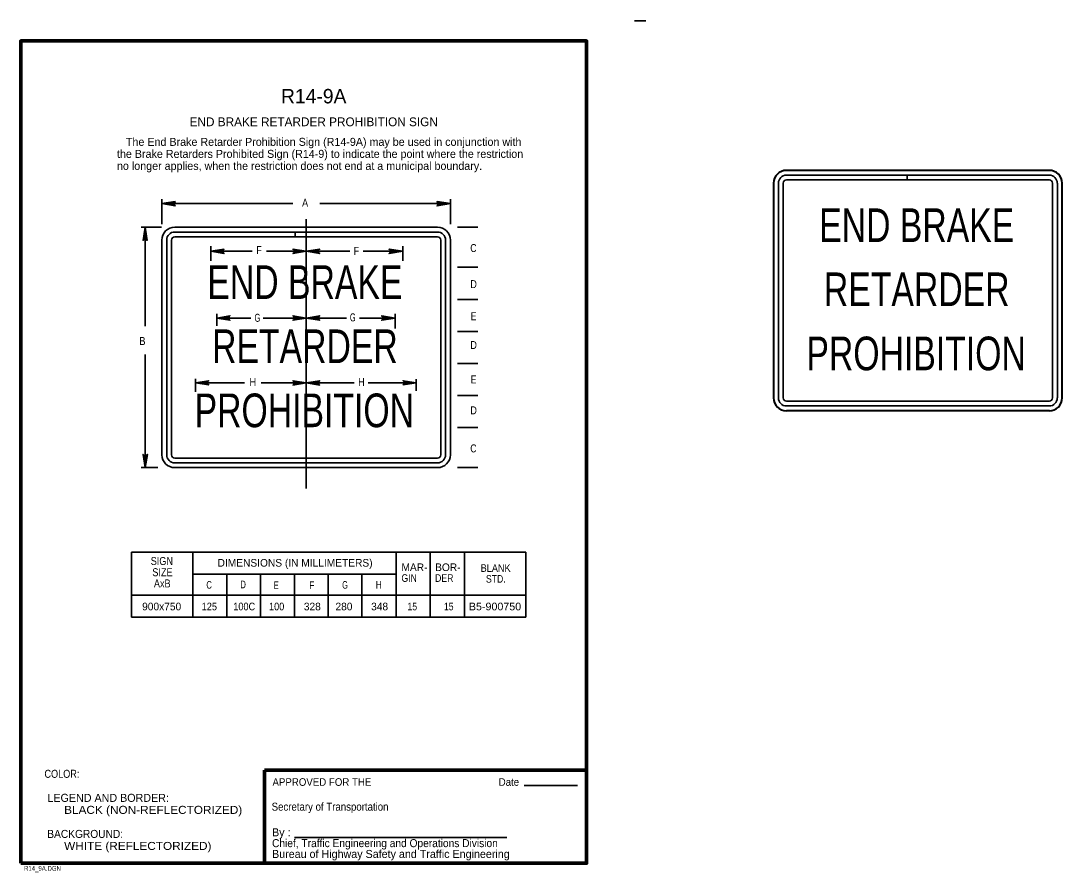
# Model space of a CAD drawing. Extents: x -0.29 to 0.3, y -0.007 to 0.262.
# Drawn here: x -0.0249 to 0.3, y -0.0038 to 0.2617 of the extents above; entities that cross this region are included whole.
import ezdxf
from ezdxf.enums import TextEntityAlignment as Align

# ---------------------------------------------------------------- set-up
doc = ezdxf.new("R2010")
doc.units = 0
doc.header["$LTSCALE"] = 0.001
doc.linetypes.add('LONG_DASH_SHORT_DASH', pattern=[9.9, 6, -1.2, 1.5, -1.2])
doc.layers.add('12', color=7, linetype='Continuous', lineweight=35)

msp = doc.modelspace()

# ---------------------------------------------------------------- linework, layer by layer
at = {"layer": '12'}
for p, q in [((0.170125, 0.26175), (0.166625, 0.26175)), ((0.296, 0.212125), (0.251625, 0.212125)), ((0.2115, 0.144125), (0.2115, 0.211125)), ((0.213, 0.211125), (0.213, 0.144125)), ((0.297, 0.144125), (0.297, 0.211125)), ((0.2985, 0.211125), (0.2985, 0.144125)), ((0.019125, 0.198375), (0.019125, 0.206125)), ((0.06, 0.20475), (0.019125, 0.20475)), ((0.109125, 0.20475), (0.068375, 0.20475)), ((0.109125, 0.198375), (0.109125, 0.206125)), ((0.019, 0.197375), (0.012625, 0.197375)), ((0.013875, 0.1665), (0.013875, 0.197375)), ((0.023125, 0.197375), (0.105125, 0.197375)), ((0.111375, 0.197375), (0.11775, 0.197375)), ((0.019125, 0.126375), (0.019125, 0.193375)), ((0.020625, 0.126375), (0.020625, 0.193375)), ((0.022125, 0.193375), (0.022125, 0.126375)), ((0.105125, 0.194375), (0.06075, 0.194375)), ((0.106125, 0.126375), (0.106125, 0.193375)), ((0.107625, 0.193375), (0.107625, 0.126375)), ((0.109125, 0.126375), (0.109125, 0.193375)), ((0.034375, 0.1915), (0.034375, 0.186875)), ((0.04725, 0.189875), (0.034375, 0.189875)), ((0.064125, 0.189875), (0.05175, 0.189875)), ((0.064125, 0.189875), (0.07775, 0.189875)), ((0.081875, 0.189875), (0.09425, 0.189875)), ((0.09425, 0.1915), (0.09425, 0.186875)), ((0.111375, 0.184875), (0.11775, 0.184875)), ((0.21, 0.17825), (0.21, 0.17)), ((0.111375, 0.174875), (0.11775, 0.174875)), ((0.03625, 0.166625), (0.03625, 0.170375)), ((0.046875, 0.169), (0.03625, 0.169)), ((0.064125, 0.169), (0.05075, 0.169)), ((0.064125, 0.169), (0.07675, 0.169)), ((0.08075, 0.169), (0.091875, 0.169)), ((0.091875, 0.16575), (0.091875, 0.170375)), ((0.111375, 0.164875), (0.11775, 0.164875)), ((0.019125, 0.1605), (0.019125, 0.15225)), ((0.013875, 0.122375), (0.013875, 0.157625)), ((0.111375, 0.154875), (0.11775, 0.154875)), ((0.029625, 0.146), (0.029625, 0.150125)), ((0.0985, 0.146375), (0.0985, 0.15)), ((0.044875, 0.148875), (0.029625, 0.148875)), ((0.064125, 0.148875), (0.050125, 0.148875)), ((0.064125, 0.148875), (0.079125, 0.148875)), ((0.0835, 0.148875), (0.0985, 0.148875)), ((0.111375, 0.144875), (0.11775, 0.144875)), ((0.214, 0.143125), (0.296, 0.143125)), ((0.296, 0.141625), (0.214, 0.141625)), ((0.111375, 0.134875), (0.11775, 0.134875)), ((0.023125, 0.125375), (0.105125, 0.125375)), ((0.105125, 0.123875), (0.023125, 0.123875)), ((0.017875, 0.122375), (0.012625, 0.122375)), ((0.105125, 0.122375), (0.023125, 0.122375)), ((0.111375, 0.122375), (0.11775, 0.122375)), ((0.009625, 0.096), (0.132625, 0.096)), ((0.009625, 0.096), (0.009625, 0.07575)), ((0.02875, 0.096), (0.02875, 0.07575)), ((0.09225, 0.096), (0.09225, 0.07575)), ((0.102875, 0.096), (0.102875, 0.07575)), ((0.1135, 0.096), (0.1135, 0.07575)), ((0.132625, 0.096), (0.132625, 0.07575)), ((0.09225, 0.089125), (0.02875, 0.089125)), ((0.039375, 0.089125), (0.039375, 0.07575)), ((0.049875, 0.089125), (0.049875, 0.07575)), ((0.0605, 0.089125), (0.0605, 0.07575)), ((0.071, 0.089125), (0.071, 0.07575)), ((0.0815, 0.089125), (0.0815, 0.07575)), ((0.009625, 0.082625), (0.132625, 0.082625)), ((0.009625, 0.07575), (0.132625, 0.07575)), ((0.132125, 0.02325), (0.14875, 0.02325)), ((0.0605, 0.007), (0.12675, 0.007))]:
    msp.add_line(p, q, dxfattribs=at)
at = {"layer": '12', "lineweight": 40}
for p, q in [((0.214, 0.215125), (0.296, 0.215125)), ((0.21, 0.144125), (0.21, 0.211125)), ((0.3, 0.144125), (0.3, 0.211125)), ((0.296, 0.140125), (0.214, 0.140125))]:
    msp.add_line(p, q, dxfattribs=at)
at = {"layer": '12', "linetype": 'LONG_DASH_SHORT_DASH'}
msp.add_line((0.064125, 0.199875), (0.064125, 0.115875), dxfattribs=at)
at = {"layer": '12', "lineweight": 70}
for q in [(0.151625, 0.028), (0.051125, -0.001)]:
    msp.add_line((0.051125, 0.028), q, dxfattribs=at)
msp.add_lwpolyline([(-0.024875, -0.001), (0.151625, -0.001), (0.151625, 0.2555), (-0.024875, 0.2555)], close=True, dxfattribs=at)
at = {"layer": '12'}
for points in [[(0.214, 0.213625), (0.251625, 0.213625), (0.251625, 0.212125), (0.214, 0.212125)], [(0.251625, 0.212125), (0.251625, 0.213625), (0.296, 0.213625)], [(0.023125, 0.205125), (0.023, 0.204875), (0.019125, 0.20475), (0.023125, 0.205125), (0.02325, 0.205375), (0.019125, 0.20475), (0.023, 0.2045), (0.023125, 0.20425), (0.019125, 0.20475), (0.02325, 0.204), (0.023125, 0.20425)], [(0.105125, 0.20425), (0.10525, 0.2045), (0.109125, 0.20475), (0.105125, 0.20425), (0.105, 0.204), (0.109125, 0.20475), (0.10525, 0.204875), (0.105125, 0.205125), (0.109125, 0.20475), (0.105, 0.205375), (0.105125, 0.205125)], [(0.013375, 0.1935), (0.013625, 0.193625), (0.013875, 0.197375), (0.013375, 0.1935), (0.01325, 0.19325), (0.013875, 0.197375), (0.014125, 0.193625), (0.014375, 0.1935), (0.013875, 0.197375), (0.0145, 0.19325), (0.014375, 0.1935)], [(0.023125, 0.195875), (0.06075, 0.195875), (0.06075, 0.194375), (0.023125, 0.194375)], [(0.06075, 0.194375), (0.06075, 0.195875), (0.105125, 0.195875)], [(0.038375, 0.190375), (0.03825, 0.19), (0.034375, 0.189875), (0.038375, 0.190375), (0.0385, 0.1905), (0.034375, 0.189875), (0.03825, 0.189625), (0.038375, 0.189375), (0.034375, 0.189875), (0.0385, 0.189125), (0.038375, 0.189375)], [(0.06025, 0.189375), (0.060375, 0.189625), (0.064125, 0.189875), (0.06025, 0.189375), (0.06, 0.189125), (0.064125, 0.189875), (0.060375, 0.19), (0.06025, 0.190375), (0.064125, 0.189875), (0.06, 0.1905), (0.06025, 0.190375)], [(0.068125, 0.189375), (0.068, 0.189625), (0.064125, 0.189875), (0.068125, 0.189375), (0.068375, 0.189125), (0.064125, 0.189875), (0.068, 0.19), (0.068125, 0.190375), (0.064125, 0.189875), (0.068375, 0.1905), (0.068125, 0.190375)], [(0.09025, 0.190375), (0.090375, 0.19), (0.09425, 0.189875), (0.09025, 0.190375), (0.09, 0.1905), (0.09425, 0.189875), (0.090375, 0.189625), (0.09025, 0.189375), (0.09425, 0.189875), (0.09, 0.189125), (0.09025, 0.189375)], [(0.040125, 0.1695), (0.04, 0.16925), (0.03625, 0.169), (0.040125, 0.1695), (0.040375, 0.16975), (0.03625, 0.169), (0.04, 0.168875), (0.040125, 0.168625), (0.03625, 0.169), (0.040375, 0.168375), (0.040125, 0.168625)], [(0.06025, 0.1685), (0.060375, 0.168875), (0.064125, 0.169), (0.06025, 0.1685), (0.06, 0.168375), (0.064125, 0.169), (0.060375, 0.16925), (0.06025, 0.1695), (0.064125, 0.169), (0.06, 0.16975), (0.06025, 0.1695)], [(0.068125, 0.1695), (0.068, 0.16925), (0.064125, 0.169), (0.068125, 0.1695), (0.068375, 0.16975), (0.064125, 0.169), (0.068, 0.168875), (0.068125, 0.168625), (0.064125, 0.169), (0.068375, 0.168375), (0.068125, 0.168625)], [(0.087875, 0.1685), (0.088125, 0.168875), (0.091875, 0.169), (0.087875, 0.1685), (0.08775, 0.168375), (0.091875, 0.169), (0.088125, 0.16925), (0.087875, 0.1695), (0.091875, 0.169), (0.08775, 0.16975), (0.087875, 0.1695)], [(0.0335, 0.149375), (0.033375, 0.149125), (0.029625, 0.148875), (0.0335, 0.149375), (0.03375, 0.1495), (0.029625, 0.148875), (0.033375, 0.148625), (0.0335, 0.148375), (0.029625, 0.148875), (0.03375, 0.14825), (0.0335, 0.148375)], [(0.06025, 0.148375), (0.060375, 0.148625), (0.064125, 0.148875), (0.06025, 0.148375), (0.06, 0.148125), (0.064125, 0.148875), (0.060375, 0.149), (0.06025, 0.149375), (0.064125, 0.148875), (0.06, 0.1495), (0.06025, 0.149375)], [(0.068125, 0.148375), (0.068, 0.148625), (0.064125, 0.148875), (0.068125, 0.148375), (0.068375, 0.148125), (0.064125, 0.148875), (0.068, 0.149), (0.068125, 0.149375), (0.064125, 0.148875), (0.068375, 0.1495), (0.068125, 0.149375)], [(0.094625, 0.149375), (0.09475, 0.149125), (0.0985, 0.148875), (0.094625, 0.149375), (0.094375, 0.1495), (0.0985, 0.148875), (0.09475, 0.148625), (0.094625, 0.148375), (0.0985, 0.148875), (0.094375, 0.14825), (0.094625, 0.148375)], [(0.014375, 0.12625), (0.014125, 0.126125), (0.013875, 0.122375), (0.014375, 0.12625), (0.014625, 0.1265), (0.013875, 0.122375), (0.01375, 0.126125), (0.013375, 0.12625), (0.013875, 0.122375), (0.01325, 0.1265), (0.013375, 0.12625)]]:
    msp.add_lwpolyline(points, dxfattribs=at)
at = {"layer": '12', "lineweight": 40}
for centre, start, end in [((0.213977, 0.211115), 90, 180), ((0.295977, 0.211115), 0, 90), ((0.213977, 0.144115), 180, 270), ((0.295977, 0.144115), 270, 0)]:
    msp.add_arc(centre, 0.004, start, end, dxfattribs=at)
at = {"layer": '12'}
for centre, radius, start, end in [((0.213977, 0.211115), 0.0025, 90, 180), ((0.213977, 0.211115), 0.001, 90, 180), ((0.295977, 0.211115), 0.0025, 0, 90), ((0.295977, 0.211115), 0.001, 0, 90), ((0.023125, 0.193375), 0.004, 90, 180), ((0.023125, 0.193375), 0.0025, 90, 180), ((0.105125, 0.193375), 0.004, 0, 90), ((0.105125, 0.193375), 0.0025, 0, 90), ((0.023125, 0.193375), 0.001, 90, 180), ((0.105125, 0.193375), 0.001, 0, 90), ((0.213977, 0.144115), 0.0025, 180, 270), ((0.213977, 0.144115), 0.001, 180, 270), ((0.295977, 0.144115), 0.0025, 270, 0), ((0.295977, 0.144115), 0.001, 270, 0), ((0.023125, 0.126375), 0.004, 180, 270), ((0.023125, 0.126375), 0.0025, 180, 270), ((0.023125, 0.126375), 0.001, 180, 270), ((0.105125, 0.126375), 0.004, 270, 0), ((0.105125, 0.126375), 0.0025, 270, 0), ((0.105125, 0.126375), 0.001, 270, 0)]:
    msp.add_arc(centre, radius, start, end, dxfattribs=at)

# ---------------------------------------------------------------- texts
for s, height, p in [('R14-9A', 0.0045, (0.0665, 0.236)), ('END BRAKE RETARDER PROHIBITION SIGN', 0.00275, (0.0665, 0.228875)), ('DIMENSIONS (IN MILLIMETERS)', 0.002375, (0.060687, 0.0915)), ('900x750', 0.002375, (0.019062, 0.077875)), ('328', 0.002375, (0.066062, 0.077875)), ('280', 0.002375, (0.075938, 0.077875)), ('348', 0.002375, (0.087063, 0.077875))]:
    msp.add_text(s, height=height, dxfattribs=at).set_placement(p, align=Align.CENTER)
for s, height, p in [('   The End Brake Retarder Prohibition Sign (R14-9A) may be used in conjunction with', 0.0025, (0.005125, 0.22275)), ('the Brake Retarders Prohibited Sign (R14-9) to indicate the point where the restriction', 0.0025, (0.005125, 0.219)), ('no longer applies, when the restriction does not end at a municipal boundary.', 0.0025, (0.005125, 0.21525)), ('MAR-', 0.002375, (0.093875, 0.090125)), ('BOR-', 0.002375, (0.104375, 0.090125)), (' LEGEND AND BORDER:', 0.0025, (-0.0175, 0.018125)), ('By :', 0.0025, (0.0535, 0.007375)), ('Bureau of Highway Safety and Traffic Engineering', 0.0025, (0.0535, 0.000625))]:
    msp.add_text(s, height=height, dxfattribs=at).set_placement(p)
for s, height, width, p in [('A', 0.002501, 0.85, (0.063813, 0.20375)), ('END BRAKE', 0.0105, 0.75, (0.254625, 0.19275)), ('C', 0.002498, 0.8, (0.116312, 0.189625)), ('F', 0.0025, 0.8, (0.049438, 0.189)), ('F', 0.0025, 0.8, (0.079813, 0.18875)), ('END BRAKE', 0.0105, 0.75, (0.06375, 0.175)), ('RETARDER', 0.0105, 0.75, (0.254625, 0.17275)), ('D', 0.002498, 0.85, (0.116375, 0.178375)), ('G', 0.0025, 0.7, (0.048938, 0.167875)), ('G', 0.0025, 0.7, (0.078688, 0.168)), ('E', 0.002498, 0.8, (0.116375, 0.168375)), ('B', 0.002501, 0.85, (0.013062, 0.160625)), ('RETARDER', 0.0105, 0.75, (0.06375, 0.155)), ('PROHIBITION', 0.0105, 0.75, (0.254437, 0.15275)), ('D', 0.002498, 0.85, (0.116375, 0.159375)), ('H', 0.0025, 0.85, (0.0475, 0.147875)), ('H', 0.0025, 0.85, (0.081375, 0.147875)), ('E', 0.002498, 0.8, (0.116375, 0.148625)), ('PROHIBITION', 0.0105, 0.75, (0.063563, 0.135)), ('D', 0.002498, 0.85, (0.116375, 0.139)), ('C', 0.002498, 0.8, (0.116312, 0.127125)), ('SIGN', 0.0025, 0.85, (0.019125, 0.092)), ('SIZE', 0.0025, 0.85, (0.019312, 0.0885)), ('BLANK', 0.002375, 0.9, (0.12325, 0.089875)), ('STD.', 0.002375, 0.85, (0.123313, 0.0865)), ('AxB', 0.0025, 0.85, (0.01925, 0.085)), ('125', 0.002375, 0.9, (0.033938, 0.077875)), ('100C', 0.002375, 0.9, (0.044812, 0.077875)), ('100', 0.002375, 0.9, (0.054938, 0.077875)), ('15', 0.002375, 0.85, (0.09725, 0.077875)), ('15', 0.002375, 0.85, (0.108625, 0.077875)), ('B5-900750', 0.002375, 1.05, (0.123063, 0.077875)), ('APPROVED FOR THE', 0.002375, 0.95, (0.069062, 0.023125)), ('Date ', 0.002375, 0.95, (0.127812, 0.023125))]:
    msp.add_text(s, height=height, dxfattribs=dict(at, width=width)).set_placement(p, align=Align.CENTER)
for s, height, width, p in [('GIN', 0.002375, 0.85, (0.093875, 0.08675)), ('DER', 0.002375, 0.85, (0.104375, 0.08675)), ('C', 0.002375, 0.75, (0.033, 0.084625)), ('D', 0.002375, 0.75, (0.043625, 0.08475)), ('E', 0.002375, 0.75, (0.054, 0.0845)), ('F', 0.002375, 0.8, (0.065125, 0.0845)), ('G', 0.002375, 0.7, (0.075375, 0.084625)), ('H', 0.002375, 0.8, (0.085875, 0.084625)), ('COLOR:', 0.0025, 0.85, (-0.0175, 0.025625)), ('      BLACK (NON-REFLECTORIZED)', 0.0025, 1.1, (-0.0175, 0.014375)), ('Secretary of Transportation', 0.0025, 0.9, (0.053375, 0.015375)), (' BACKGROUND:', 0.0025, 0.95, (-0.0175, 0.006875)), ('Chief, Traffic Engineering and Operations Division', 0.0025, 0.95, (0.0535, 0.004)), ('      WHITE (REFLECTORIZED)', 0.0025, 1.1, (-0.0175, 0.003125)), ('R14_9A.DGN', 0.0015, 0.75, (-0.023875, -0.003375))]:
    msp.add_text(s, height=height, dxfattribs=dict(at, width=width)).set_placement(p)

doc.saveas('drawing.dxf')
